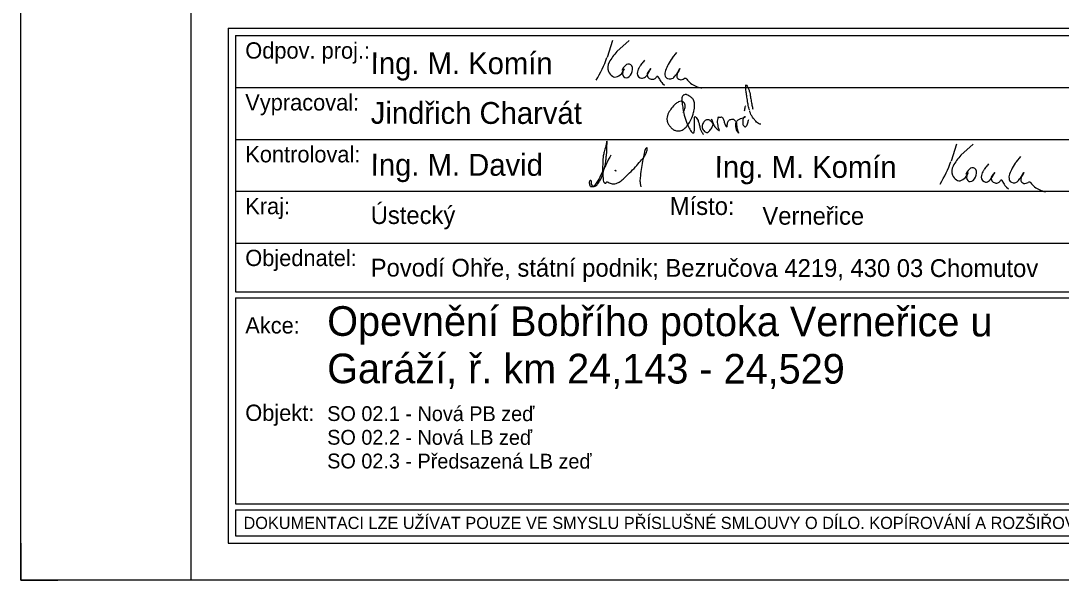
# Model space of a CAD drawing. Extents: x 67.3 to 115.4, y -93.9 to -78.3.
# Drawn here: x 92.28 to 99.3, y -93.93 to -90.16 of the extents above; entities that cross this region are included whole.
import ezdxf

# ---------------------------------------------------------------- set-up
doc = ezdxf.new("R2010")
doc.units = 0
for name, color, linetype in [('07_rozpiska', 7, 'Continuous'), ('07_rámeček', 7, 'Continuous'), ('Default', 7, 'Continuous'), ('Rozpiska + rámeček', 7, 'Continuous')]:
    doc.layers.add(name, color=color, linetype=linetype)

# ---------------------------------------------------------------- blocks, each defined once
blk = doc.blocks.new('Charvat')
at = {"layer": 'Rozpiska + rámeček'}
for points in [[(0.0826, 0.02), (0.0817, 0.0228), (0.0806, 0.0281), (0.0796, 0.0345), (0.0789, 0.0395), (0.0784, 0.0445), (0.0784, 0.0456), (0.0785, 0.0469), (0.0787, 0.0476), (0.0791, 0.0473), (0.0804, 0.0456), (0.0816, 0.0427), (0.0827, 0.0394), (0.0832, 0.0363), (0.0841, 0.0314), (0.0846, 0.0282), (0.0855, 0.0238), (0.086, 0.0216)], [(0.0108, 0.0178), (0.0123, 0.0208), (0.0129, 0.0234), (0.0122, 0.0279), (0.0108, 0.0294), (0.0087, 0.0301), (0.0059, 0.0293), (0.0024, 0.0271), (-0.0017, 0.0225), (-0.0049, 0.0177), (-0.0062, 0.0145), (-0.0067, 0.0115), (-0.0063, 0.0075), (-0.0059, 0.0064), (-0.0039, 0.0034), (-0.0014, 0.0007), (0.001, -0.001), (0.0043, -0.0019), (0.0075, -0.0019), (0.0097, -0.001), (0.0131, 0.0013), (0.0158, 0.0045), (0.0192, 0.0101), (0.022, 0.0182), (0.0223, 0.0193), (0.023, 0.0256), (0.0227, 0.0293), (0.0219, 0.0315), (0.0199, 0.034), (0.017, 0.036), (0.0147, 0.0371), (0.0142, 0.0372), (0.013, 0.0373), (0.0113, 0.0368), (0.0106, 0.0362), (0.0097, 0.0348), (0.0095, 0.0343), (0.0093, 0.0333), (0.0093, 0.0314), (0.0096, 0.0279), (0.0105, 0.0221), (0.012, 0.0151), (0.0133, 0.0108), (0.0166, 0.0023), (0.0195, -0.0026), (0.0202, -0.0035), (0.0214, -0.0042), (0.022, -0.0042), (0.0225, -0.0034), (0.023, -0.0014), (0.0231, 0), (0.0231, 0.0051), (0.0231, 0.0111), (0.0231, 0.0124), (0.0233, 0.0132), (0.0236, 0.0135), (0.024, 0.0133), (0.0254, 0.0115), (0.0268, 0.0092), (0.0279, 0.0059), (0.0289, 0.0018), (0.0298, -0.0012), (0.0315, -0.0041), (0.0327, -0.0059)], [(0.0771, 0.0198), (0.0779, 0.024), (0.0784, 0.0252)], [(0.0428, 0.0062), (0.0417, 0.0075), (0.0401, 0.009), (0.0394, 0.0095), (0.0378, 0.0101), (0.0368, 0.0101), (0.0353, 0.0098), (0.034, 0.0088), (0.0326, 0.0071), (0.0316, 0.0051), (0.0313, 0.0026), (0.0313, 0.0011), (0.0322, -0.0007), (0.0338, -0.0025), (0.0354, -0.0034), (0.0366, -0.0037), (0.0381, -0.0031), (0.0397, -0.0014), (0.0411, 0.0004), (0.0422, 0.0025), (0.043, 0.005), (0.043, 0.0063), (0.0429, 0.0069), (0.0424, 0.0086), (0.0414, 0.0106), (0.0421, 0.009), (0.0433, 0.0053), (0.0444, 0.0034), (0.0458, 0.0017), (0.0476, 0), (0.0497, -0.0015), (0.0498, -0.0016), (0.0499, -0.0016), (0.0499, -0.0014), (0.0492, 0.0003), (0.0487, 0.0022), (0.0482, 0.0055), (0.048, 0.0086), (0.0484, 0.0114), (0.0491, 0.0131), (0.0493, 0.013), (0.0506, 0.0127), (0.0522, 0.0131), (0.0539, 0.0111), (0.0547, 0.0094), (0.0552, 0.0074), (0.0556, 0.0056), (0.0566, 0.0038), (0.058, 0.0025), (0.0582, 0.0031), (0.0585, 0.0057), (0.0589, 0.0076), (0.0593, 0.0083), (0.0604, 0.0095), (0.0616, 0.0102), (0.0632, 0.0106), (0.065, 0.0106), (0.0665, 0.0094), (0.0678, 0.0078), (0.0686, 0.0033), (0.0691, 0.0001), (0.0701, -0.0031), (0.0705, -0.0044), (0.0697, -0.0035), (0.0682, -0.0005), (0.0677, 0.0025), (0.0677, 0.0059), (0.0683, 0.0079), (0.0702, 0.01), (0.0728, 0.0114), (0.0756, 0.0122), (0.0781, 0.0133), (0.0764, 0.0125), (0.0755, 0.0112), (0.0751, 0.0096), (0.0751, 0.0075), (0.0753, 0.005), (0.0753, 0.0048), (0.0758, 0.0038), (0.0766, 0.003), (0.0772, 0.0026), (0.0776, 0.0025), (0.0783, 0.0027), (0.0791, 0.0034), (0.0799, 0.0047), (0.0806, 0.0069), (0.0816, 0.0104)], [(0.0947, 0.0053), (0.0934, 0.0053), (0.0921, 0.0059), (0.0901, 0.0076), (0.0883, 0.0095), (0.0858, 0.0127), (0.0839, 0.0159), (0.0829, 0.0186), (0.0827, 0.0193)]]:
    blk.add_spline(points, degree=3, dxfattribs=at)

msp = doc.modelspace()

# ---------------------------------------------------------------- linework, layer by layer
at = {"layer": '07_rozpiska'}
for points in [[(96.2374, -90.9979), (96.2387, -90.9881), (96.2381, -90.9684), (96.2303, -90.9992), (96.2199, -91.0413), (96.2138, -91.0675), (96.2105, -91.1112), (96.2089, -91.1469), (96.2121, -91.2214), (96.2154, -91.2411), (96.228, -91.2528), (96.2325, -91.2496), (96.2335, -91.2473), (96.2406, -91.2424), (96.2533, -91.2489), (96.2669, -91.2544), (96.2818, -91.257), (96.2999, -91.2541), (96.3203, -91.2457), (96.3469, -91.2243), (96.3906, -91.1832), (96.4308, -91.142), (96.4648, -91.1035), (96.4923, -91.0701), (96.5072, -91.0371), (96.5108, -91.0209), (96.5095, -91.0141), (96.5034, -91.0154), (96.4927, -91.0387), (96.4868, -91.0626), (96.4781, -91.1044), (96.4693, -91.1601), (96.4622, -91.2162), (96.4616, -91.245), (96.4651, -91.2667), (96.4671, -91.2774)], [(96.2313, -91.1031), (96.2332, -91.0772), (96.2358, -91.0546), (96.2377, -91.0303), (96.2374, -90.9979)], [(96.2636, -91.0636), (96.2361, -91.1184), (96.1898, -91.2104), (96.1564, -91.2648), (96.1441, -91.2761), (96.1347, -91.2777), (96.1289, -91.2771), (96.1247, -91.2703), (96.1227, -91.2583)], [(96.1227, -91.2583), (96.1208, -91.2466), (96.1218, -91.2389), (96.1266, -91.2324), (96.1302, -91.2317), (96.1321, -91.2437), (96.1328, -91.258), (96.1409, -91.2703), (96.1522, -91.2745), (96.1629, -91.2706), (96.1723, -91.2628), (96.1775, -91.256), (96.1927, -91.2317), (96.1989, -91.2201), (96.2147, -91.1738), (96.2313, -91.1031)], [(96.296, -91.1653), (96.2938, -91.1663), (96.2938, -91.1683), (96.2954, -91.1692), (96.2986, -91.1699), (96.2993, -91.1683), (96.2993, -91.1666), (96.296, -91.1653)]]:
    msp.add_spline(points, degree=3, dxfattribs=at)
at = {"layer": 'Default'}
for p, q in [((96.3404, -90.5049), (96.3548, -90.479)), ((96.5824, -90.5337), (96.5924, -90.551)), ((96.614, -90.5798), (96.6256, -90.5913)), ((98.6621, -91.2049), (98.6765, -91.179)), ((98.9041, -91.2337), (98.9141, -91.251)), ((98.9357, -91.2798), (98.9473, -91.2913))]:
    msp.add_line(p, q, dxfattribs=at)
for points in [[(96.2756, -90.2889), (96.2396, -90.4041)], [(96.388, -90.2889), (96.3044, -90.3638)], [(96.4916, -90.4214), (96.4816, -90.4358)], [(96.7076, -90.371), (96.6788, -90.407)], [(96.4628, -90.4617), (96.46, -90.4646)], [(96.5132, -90.5049), (96.5132, -90.5078)], [(96.5276, -90.4905), (96.5348, -90.479), (96.5248, -90.4905)], [(96.7048, -90.5222), (96.7292, -90.479), (96.7192, -90.5049)], [(96.5104, -90.5222), (96.5104, -90.5222)], [(98.5973, -90.9889), (98.5613, -91.1041)], [(98.7097, -90.9889), (98.6261, -91.0638)], [(99.0293, -91.071), (99.0005, -91.107)], [(98.8133, -91.1214), (98.8033, -91.1358)], [(98.7845, -91.1617), (98.7817, -91.1646)], [(98.8349, -91.2049), (98.8349, -91.2078)], [(98.8493, -91.1905), (98.8565, -91.179), (98.8465, -91.1905)], [(99.0265, -91.2222), (99.0509, -91.179), (99.0409, -91.2049)], [(98.8321, -91.2222), (98.8321, -91.2222)]]:
    msp.add_lwpolyline(points, dxfattribs=at)
for centre, radius, start, end in [((96.5645, -90.6056), 0.3545, 137.00062, 151.51062), ((95.3063, -90.0574), 0.9948, 329.80858, 339.56815), ((96.3168, -90.4722), 0.0732, 150.83631, 201.23374), ((96.7033, -90.6186), 0.288, 140.57196, 146.46893), ((96.9105, -90.5927), 0.2956, 141.11668, 151.43002), ((96.3233, -90.4626), 0.083, 205.78195, 234.22418), ((96.2725, -90.4548), 0.0864, 295.93387, 323.63221), ((96.4177, -90.5204), 0.084, 133.12102, 160.6603), ((96.3969, -90.5127), 0.0529, 142.82783, 193.29225), ((96.5486, -90.5272), 0.1085, 146.31446, 165.71836), ((96.2186, -90.3072), 0.288, 326.31446, 326.46946), ((96.3598, -90.4115), 0.1862, 320.58833, 335.16259), ((96.5391, -90.5192), 0.0288, 154.94151, 187.17365), ((96.5663, -90.529), 0.0576, 139.19606, 154.94016), ((96.6914, -90.5134), 0.0617, 158.78845, 195.14726), ((96.8323, -90.5521), 0.2075, 150.931, 162.8917), ((96.7766, -90.5367), 0.0677, 151.17648, 169.00349), ((96.2949, -90.499), 0.0369, 236.98468, 294.62862), ((96.3348, -90.6162), 0.0864, 108.04736, 108.08265), ((96.4753, -90.5122), 0.0323, 245.35778, 276.92267), ((96.4682, -90.4981), 0.0475, 283.31943, 318.16716), ((96.5391, -90.5205), 0.0286, 186.45097, 212.31824), ((96.5423, -90.5186), 0.0324, 212.08411, 258.70933), ((96.5439, -90.515), 0.0362, 257.35338, 296.27075), ((96.5376, -90.5108), 0.043, 301.37529, 327.02531), ((96.5787, -90.5371), 0.00576, 26.63136, 150.41952), ((96.6699, -90.5135), 0.0864, 206.63144, 229.82938), ((96.6572, -90.5215), 0.0265, 197.61582, 249.38851), ((96.6636, -90.5028), 0.0463, 250.12564, 275.82035), ((96.6643, -90.514), 0.035, 276.59581, 304.89281), ((96.6225, -90.4655), 0.099, 308.6573, 325.5075), ((96.7396, -90.5279), 0.0297, 172.16185, 218.17447), ((96.7388, -90.5195), 0.0349, 229.93747, 256.22885), ((96.7349, -90.5079), 0.0458, 264.36538, 302.31991), ((96.7665, -90.5581), 0.0136, 38.96313, 121.674), ((96.8859, -90.4734), 0.1329, 214.99845, 231.36881), ((96.9225, -90.4078), 0.2073, 234.79421, 256.99308), ((98.8862, -91.3056), 0.3545, 137.00062, 151.51062), ((97.628, -90.7574), 0.9948, 329.80858, 339.56815), ((98.6385, -91.1722), 0.0732, 150.83631, 201.23374), ((99.025, -91.3186), 0.288, 140.57196, 146.46893), ((99.2322, -91.2927), 0.2956, 141.11668, 151.43002), ((98.645, -91.1626), 0.083, 205.78195, 234.22418), ((98.5942, -91.1548), 0.0864, 295.93387, 323.63221), ((98.7394, -91.2204), 0.084, 133.12102, 160.6603), ((98.7186, -91.2127), 0.0529, 142.82783, 193.29225), ((98.8703, -91.2272), 0.1085, 146.31446, 165.71836), ((98.5403, -91.0072), 0.288, 326.31446, 326.46946), ((98.6814, -91.1115), 0.1862, 320.58833, 335.16259), ((98.8608, -91.2192), 0.0288, 154.94151, 187.17365), ((98.888, -91.229), 0.0576, 139.19606, 154.94016), ((99.0131, -91.2134), 0.0617, 158.78845, 195.14726), ((99.154, -91.2521), 0.2075, 150.931, 162.8917), ((99.0983, -91.2367), 0.0677, 151.17648, 169.00349), ((98.6166, -91.199), 0.0369, 236.98468, 294.62862), ((98.6565, -91.3162), 0.0864, 108.04736, 108.08265), ((98.797, -91.2122), 0.0323, 245.35778, 276.92267), ((98.7899, -91.1981), 0.0475, 283.31943, 318.16716), ((98.8608, -91.2205), 0.0286, 186.45097, 212.31824), ((98.864, -91.2186), 0.0324, 212.08411, 258.70933), ((98.8656, -91.215), 0.0362, 257.35338, 296.27075), ((98.8593, -91.2108), 0.043, 301.37529, 327.02531), ((98.9003, -91.2371), 0.00576, 26.63136, 150.41952), ((98.9916, -91.2135), 0.0864, 206.63144, 229.82938), ((98.9789, -91.2215), 0.0265, 197.61582, 249.38851), ((98.9853, -91.2028), 0.0463, 250.12564, 275.82035), ((98.986, -91.214), 0.035, 276.59581, 304.89281), ((98.9442, -91.1655), 0.099, 308.6573, 325.5075), ((99.0613, -91.2279), 0.0297, 172.16185, 218.17447), ((99.0604, -91.2195), 0.0349, 229.93747, 256.22885), ((99.0566, -91.2079), 0.0458, 264.36538, 302.31991), ((99.0882, -91.2581), 0.0136, 38.96313, 121.674), ((99.2076, -91.1734), 0.1329, 214.99845, 231.36881), ((99.2442, -91.1078), 0.2073, 234.79421, 256.99308)]:
    msp.add_arc(centre, radius, start, end, dxfattribs=at)
for centre, major_axis, ratio, start_param, end_param in [((96.3764, -90.4946), (0.0152, 0.0459), 0.677007, 2.488228, 7.220838), ((96.4791, -90.5113), (-0.0357, 0.0109), 0.932374, 0, 1.363098), ((98.6981, -91.1946), (0.0152, 0.0459), 0.677007, 2.488228, 7.220838), ((98.8008, -91.2113), (-0.0357, 0.0109), 0.932374, 0, 1.363098)]:
    msp.add_ellipse(centre, major_axis=major_axis, ratio=ratio, start_param=start_param, end_param=end_param, dxfattribs=at)
at = {"layer": 'Rozpiska + rámeček'}
for p, q in [((93.6823, -90.2063), (93.6823, -93.6813)), ((93.6823, -90.2063), (102.2823, -90.2063)), ((93.7323, -90.2563), (93.7323, -91.9863)), ((93.7323, -90.2563), (99.3923, -90.2563)), ((93.7323, -90.6063), (99.3923, -90.6063)), ((93.7323, -90.9563), (99.3923, -90.9563)), ((93.7323, -91.3063), (99.3923, -91.3063)), ((93.7323, -91.6563), (99.3923, -91.6563)), ((93.7323, -91.9863), (99.3923, -91.9863)), ((93.7323, -92.0263), (99.3923, -92.0263)), ((93.7323, -92.0263), (93.7323, -93.4163)), ((93.7323, -93.4163), (99.3923, -93.4163)), ((93.7323, -93.4563), (102.2323, -93.4563)), ((93.7323, -93.4563), (93.7323, -93.6313)), ((93.7323, -93.6313), (102.2323, -93.6313)), ((93.6823, -93.6813), (102.2823, -93.6813))]:
    msp.add_line(p, q, dxfattribs=at)
for points in [[(92.2823, -79.0813), (102.7823, -79.0813), (102.7823, -93.9313), (92.2823, -93.9313)], [(93.4323, -86.5063), (102.5323, -86.5063), (102.5323, -93.9313), (93.4323, -93.9313)]]:
    msp.add_lwpolyline(points, close=True, dxfattribs=at)
msp.add_lwpolyline([(92.2823, -93.6813), (92.2823, -93.9313), (92.5323, -93.9313)], dxfattribs=at)

# ---------------------------------------------------------------- block references
at = {"layer": '07_rámeček', "xscale": 6.250000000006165, "yscale": 6.250000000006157, "rotation": 3.739011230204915e-09}
msp.add_blockref('Charvat', (96.6853, -90.887), dxfattribs=at)

# ---------------------------------------------------------------- texts
at = {"layer": '07_rozpiska'}
for s, height, p in [('Opevnění Bobřího potoka Verneřice u ', 0.2, (94.3503, -92.2822)), ('Garáží, ř. km 24,143 - 24,529', 0.2, (94.3501, -92.6022)), ('SO 02.1 - Nová PB zeď', 0.1, (94.3504, -92.8569)), ('SO 02.2 - Nová LB zeď', 0.1, (94.3503, -93.0169)), ('SO 02.3 - Předsazená LB zeď', 0.1, (94.3502, -93.1769))]:
    msp.add_text(s, height=height, rotation=359.95393, dxfattribs=at).set_placement(p)
at = {"layer": 'Rozpiska + rámeček'}
for s, height, rotation, p in [('Odpov. proj.:', 0.11, 359.95393, (93.7973, -90.4113)), ('Ing. M. Komín', 0.147465, 359.95278, (94.644, -90.5157)), ('Vypracoval:', 0.11, 359.95393, (93.7973, -90.7613)), ('Jindřich Charvát', 0.147465, 359.95278, (94.644, -90.8513)), ('Kontroloval:', 0.11, 359.95393, (93.7973, -91.1113)), ('Ing. M. David', 0.147465, 359.95278, (94.644, -91.2013)), ('Ing. M. Komín', 0.147465, 359.95278, (96.9657, -91.2157)), ('Kraj:', 0.11, 359.95393, (93.7973, -91.4613)), ('Místo:', 0.12, 359.95393, (96.6623, -91.4663)), ('Ústecký', 0.12, 359.95393, (94.644, -91.5273)), ('Verneřice', 0.12, 359.95278, (97.2873, -91.5321)), ('Objednatel:', 0.11, 359.95393, (93.7973, -91.8113)), ('Povodí Ohře, státní podnik; Bezručova 4219, 430 03 Chomutov', 0.12, 359.95278, (94.644, -91.8821)), ('Akce:', 0.11, 359.95393, (93.7973, -92.2663)), ('Objekt:', 0.11, 359.95393, (93.7973, -92.8564))]:
    msp.add_text(s, height=height, rotation=rotation, dxfattribs=at).set_placement(p)
msp.add_text('DOKUMENTACI LZE UŽÍVAT POUZE VE SMYSLU PŘÍSLUŠNÉ SMLOUVY O DÍLO. KOPÍROVÁNÍ A ROZŠIŘOVÁNÍ POUZE PO PŘEDCHOZÍM SOUHLASU  AZ CONSULT spol. s. r.o.', height=0.0822563, dxfattribs=at).set_placement((93.7853, -93.5859))

doc.saveas('drawing.dxf')
